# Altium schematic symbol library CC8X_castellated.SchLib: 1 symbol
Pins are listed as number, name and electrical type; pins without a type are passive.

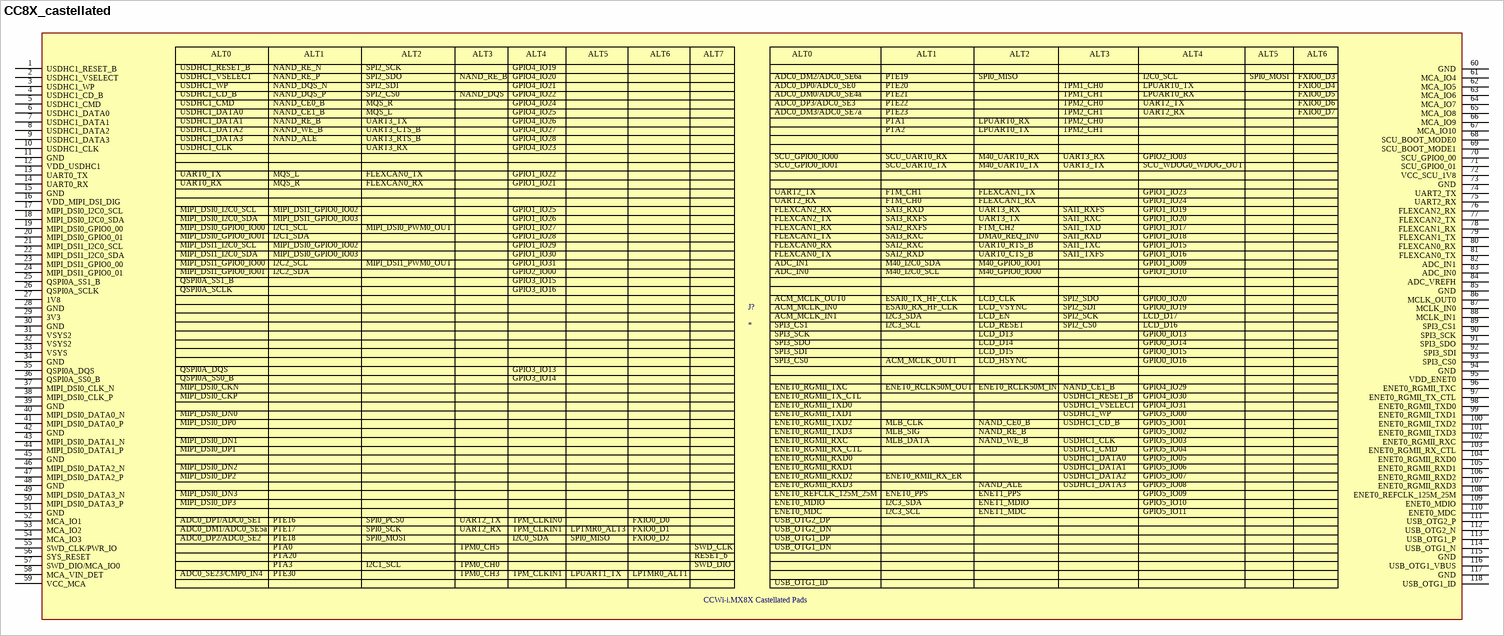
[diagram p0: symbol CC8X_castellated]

## CC8X_castellated
designator J?
CC8X
pins: 1 USDHC1_RESET_B, 2 USDHC1_VSELECT, 3 USDHC1_WP, 4 USDHC1_CD_B, 5 USDHC1_CMD, 6 USDHC1_DATA0, 7 USDHC1_DATA1, 8 USDHC1_DATA2, 9 USDHC1_DATA3, 10 USDHC1_CLK, 11 GND, 12 VDD_USDHC1, 13 UART0_TX, 14 UART0_RX, 15 GND, 16 VDD_MIPI_DSI_DIG, 17 MIPI_DSI0_I2C0_SCL, 18 MIPI_DSI0_I2C0_SDA, 19 MIPI_DSI0_GPIO0_00, 20 MIPI_DSI0_GPIO0_01, 21 MIPI_DSI1_I2C0_SCL, 22 MIPI_DSI1_I2C0_SDA, 23 MIPI_DSI1_GPIO0_00, 24 MIPI_DSI1_GPIO0_01, 25 QSPI0A_SS1_B, 26 QSPI0A_SCLK, 27 1V8, 28 GND, 29 3V3, 30 GND, 31 VSYS2, 32 VSYS2, 33 VSYS, 34 GND, 35 QSPI0A_DQS, 36 QSPI0A_SS0_B, 37 MIPI_DSI0_CLK_N, 38 MIPI_DSI0_CLK_P, 39 GND, 40 MIPI_DSI0_DATA0_N, 41 MIPI_DSI0_DATA0_P, 42 GND, 43 MIPI_DSI0_DATA1_N, 44 MIPI_DSI0_DATA1_P, 45 GND, 46 MIPI_DSI0_DATA2_N, 47 MIPI_DSI0_DATA2_P, 48 GND, 49 MIPI_DSI0_DATA3_N, 50 MIPI_DSI0_DATA3_P, 51 GND, 52 MCA_IO1, 53 MCA_IO2, 54 MCA_IO3, 55 SWD_CLK/PWR_IO, 56 SYS_RESET, 57 SWD_DIO/MCA_IO0, 58 MCA_VIN_DET, 59 VCC_MCA, 60 GND, 61 MCA_IO4, 62 MCA_IO5, 63 MCA_IO6, 64 MCA_IO7, 65 MCA_IO8, 66 MCA_IO9, 67 MCA_IO10, 68 SCU_BOOT_MODE0, 69 SCU_BOOT_MODE1, 70 SCU_GPIO0_00, 71 SCU_GPIO0_01, 72 VCC_SCU_1V8, 73 GND, 74 UART2_TX, 75 UART2_RX, 76 FLEXCAN2_RX, 77 FLEXCAN2_TX, 78 FLEXCAN1_RX, 79 FLEXCAN1_TX, 80 FLEXCAN0_RX, 81 FLEXCAN0_TX, 82 ADC_IN1, 83 ADC_IN0, 84 ADC_VREFH, 85 GND, 86 MCLK_OUT0, 87 MCLK_IN0, 88 MCLK_IN1, 89 SPI3_CS1, 90 SPI3_SCK, 91 SPI3_SDO, 92 SPI3_SDI, 93 SPI3_CS0, 94 GND, 95 VDD_ENET0, 96 ENET0_RGMII_TXC, 97 ENET0_RGMII_TX_CTL, 98 ENET0_RGMII_TXD0, 99 ENET0_RGMII_TXD1, 100 ENET0_RGMII_TXD2, 101 ENET0_RGMII_TXD3, 102 ENET0_RGMII_RXC, 103 ENET0_RGMII_RX_CTL, 104 ENET0_RGMII_RXD0, 105 ENET0_RGMII_RXD1, 106 ENET0_RGMII_RXD2, 107 ENET0_RGMII_RXD3, 108 ENET0_REFCLK_125M_25M, 109 ENET0_MDIO, 110 ENET0_MDC, 111 USB_OTG2_P, 112 USB_OTG2_N, 113 USB_OTG1_P, 114 USB_OTG1_N, 115 GND, 116 USB_OTG1_VBUS, 117 GND, 118 USB_OTG1_ID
